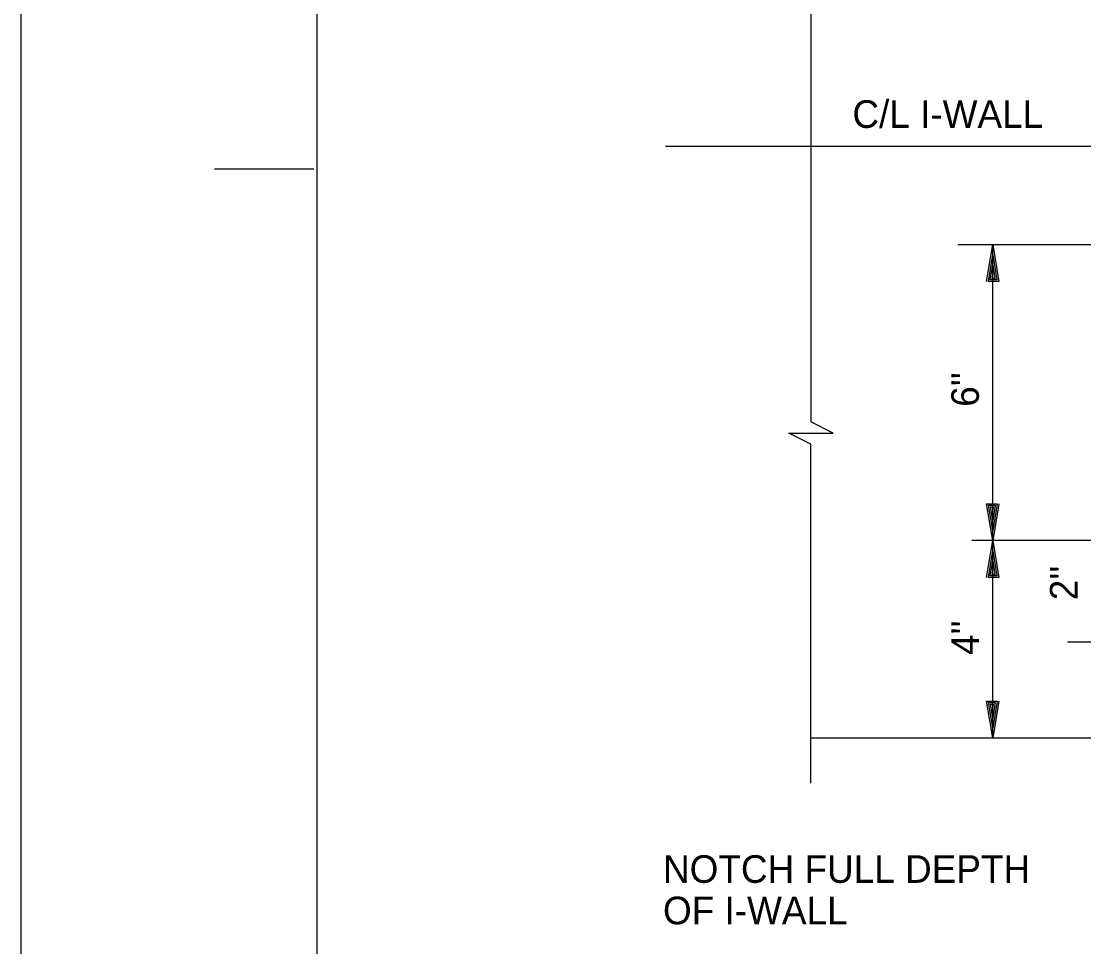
# Model space of a CAD drawing. Extents: x 22369.6 to 22428.3, y 22369.6 to 22415.
# Drawn here: x 22369.62 to 22376.81, y 22376.03 to 22382.28 of the extents above; entities that cross this region are included whole.
import ezdxf

# ---------------------------------------------------------------- set-up
doc = ezdxf.new("R2010")
doc.units = 0
for name, color, linetype in [('Level 1', 7, 'Continuous'), ('Level 10', 7, 'Continuous'), ('Level 4', 7, 'Continuous'), ('Level 9', 7, 'Continuous')]:
    doc.layers.add(name, color=color, linetype=linetype)

msp = doc.modelspace()

# ---------------------------------------------------------------- linework, layer by layer
at = {"layer": 'Level 1'}
for p, q in [((22374.9604, 22383.3905), (22374.9604, 22379.5761)), ((22373.9766, 22381.4406), (22376.9889, 22381.4406)), ((22375.953, 22380.7739), (22378.7984, 22380.7739)), ((22376.1896, 22378.7739), (22376.1896, 22380.7739)), ((22376.1896, 22380.7739), (22376.1896, 22380.7739)), ((22376.1896, 22380.7046), (22376.1896, 22380.7046)), ((22374.9604, 22377.1355), (22374.9604, 22379.4266)), ((22376.1896, 22378.8433), (22376.1896, 22378.8433)), ((22377.6825, 22378.7739), (22376.0484, 22378.7739)), ((22376.1896, 22377.4406), (22376.1896, 22378.7739)), ((22376.1896, 22378.7739), (22376.1896, 22378.7739)), ((22376.1896, 22378.7739), (22376.1896, 22378.7739)), ((22376.1896, 22378.7046), (22376.1896, 22378.7046)), ((22378.3577, 22378.0881), (22376.6958, 22378.0881)), ((22376.1896, 22377.5099), (22376.1896, 22377.5099)), ((22376.1896, 22377.4406), (22376.1896, 22377.4406))]:
    msp.add_line(p, q, dxfattribs=at)
msp.add_lwpolyline([(22369.6213, 22414.9653), (22428.2885, 22414.9653), (22428.2885, 22369.6213), (22369.6213, 22369.6213)], close=True, dxfattribs=at)
for points in [[(22376.1482, 22380.5246), (22376.1896, 22380.7739), (22376.2309, 22380.5246), (22376.1602, 22380.5246), (22376.1896, 22380.7046), (22376.2176, 22380.5353), (22376.1722, 22380.5353), (22376.1896, 22380.6379), (22376.2042, 22380.5459), (22376.1856, 22380.5459), (22376.1896, 22380.5686)], [(22374.9604, 22379.4266), (22374.8104, 22379.5011), (22375.1101, 22379.5011), (22374.9604, 22379.5761)], [(22376.2309, 22379.0233), (22376.1896, 22378.7739), (22376.1482, 22379.0233), (22376.2189, 22379.0233), (22376.1896, 22378.8433), (22376.1616, 22379.0126), (22376.2069, 22379.0126), (22376.1896, 22378.9099), (22376.1749, 22379.0019), (22376.1936, 22379.0019), (22376.1896, 22378.9793)], [(22376.1482, 22378.5246), (22376.1896, 22378.7739), (22376.2309, 22378.5246), (22376.1602, 22378.5246), (22376.1896, 22378.7046), (22376.2176, 22378.5353), (22376.1722, 22378.5353), (22376.1896, 22378.6379), (22376.2042, 22378.5459), (22376.1856, 22378.5459), (22376.1896, 22378.5686)], [(22376.2309, 22377.6899), (22376.1896, 22377.4406), (22376.1482, 22377.6899), (22376.2189, 22377.6899), (22376.1896, 22377.5099), (22376.1616, 22377.6793), (22376.2069, 22377.6793), (22376.1896, 22377.5766), (22376.1749, 22377.6686), (22376.1936, 22377.6686), (22376.1896, 22377.6459)]]:
    msp.add_lwpolyline(points, dxfattribs=at)
at = {"layer": 'Level 10'}
for p, q in [((22370.9285, 22381.2853), (22371.6005, 22381.2853)), ((22374.9604, 22377.4406), (22377.5437, 22377.4406))]:
    msp.add_line(p, q, dxfattribs=at)
at = {"layer": 'Level 9'}
msp.add_line((22371.6213, 22370.2933), (22371.6213, 22414.2933), dxfattribs=at)

# ---------------------------------------------------------------- texts
at = {"layer": 'Level 4'}
for s, height, p in [('C/L I-WALL', 0.18667, (22375.2409, 22381.563)), ('NOTCH FULL DEPTH', 0.186667, (22373.9602, 22376.4614)), ('OF I-WALL', 0.18667, (22373.9602, 22376.1814))]:
    msp.add_text(s, height=height, dxfattribs=at).set_placement(p)
for s, p in [("6''", (22376.0962, 22379.6783)), ("2''", (22376.7629, 22378.371)), ("4''", (22376.0962, 22378.001))]:
    msp.add_text(s, height=0.18667, rotation=90, dxfattribs=at).set_placement(p)

doc.saveas('drawing.dxf')
